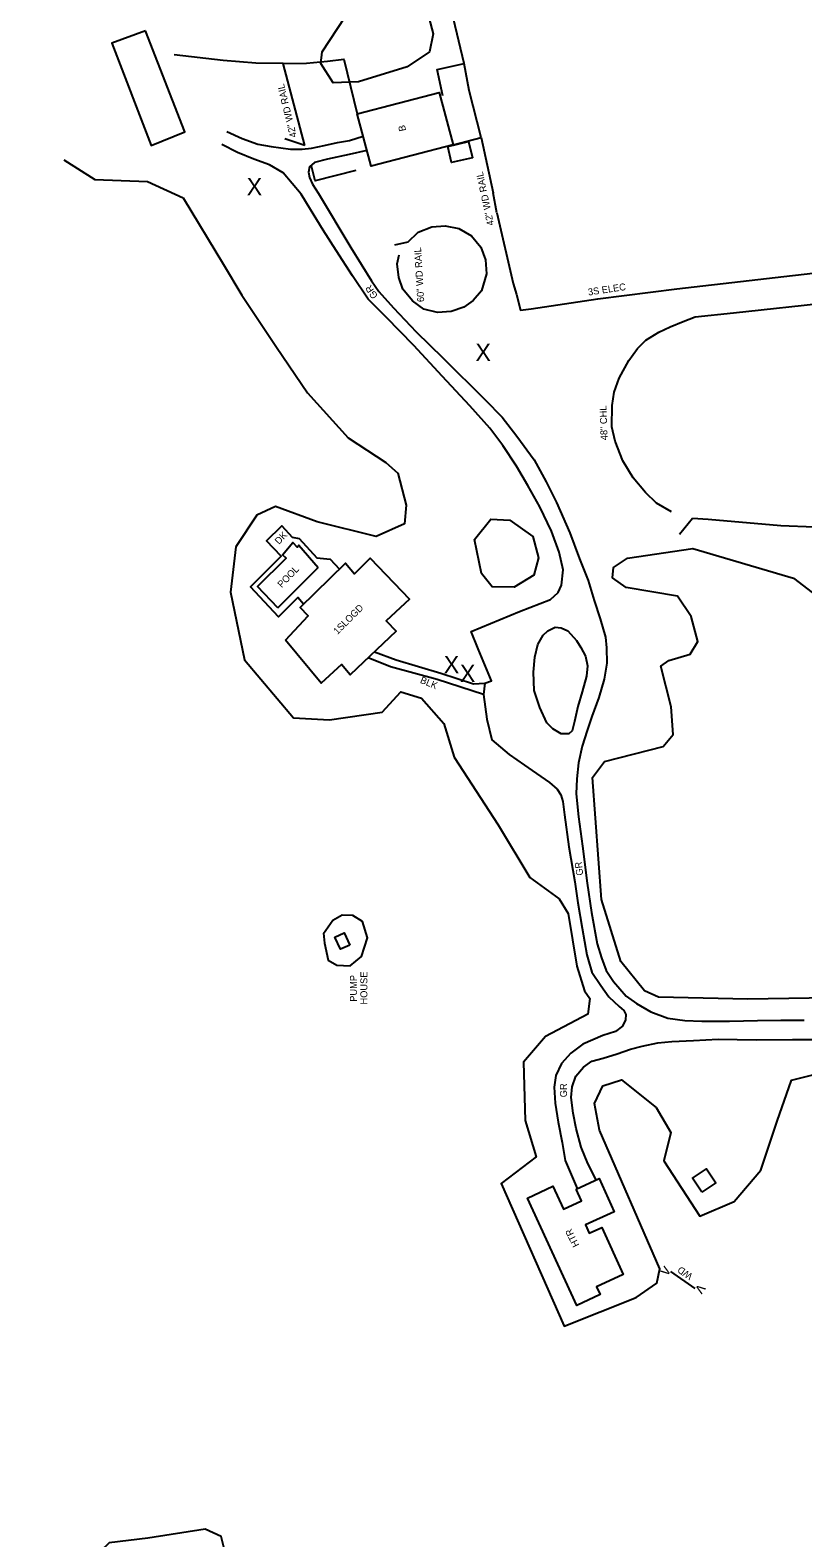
# Model space of a CAD drawing. Extents: x 2030130 to 2036320, y 723205 to 762423.
# Drawn here: x 2033438 to 2033884, y 736507 to 737377 of the extents above; entities that cross this region are included whole.
import ezdxf

# ---------------------------------------------------------------- set-up
doc = ezdxf.new("R2010")
doc.units = 0
for name, color, linetype in [('Draft_Station Labels Major', 7, 'Continuous'), ('Draft_Station Tics Major', 7, 'Continuous'), ('Draft_Station Tics Minor', 7, 'Continuous'), ('Exist Terrain Model Ground Surface', 7, 'Continuous'), ('Old_Level_23', 7, 'Continuous'), ('Old_Level_28', 7, 'Continuous'), ('Prop Alignment Horizontal', 7, 'Continuous'), ('Prop Alignment Vertical', 7, 'Continuous')]:
    doc.layers.add(name, color=color, linetype=linetype)

msp = doc.modelspace()

# ---------------------------------------------------------------- linework, layer by layer
at = {"layer": 'Draft_Station Labels Major'}
for points in [[(2033551.47, 737318.7), (2033560.28, 737314.7), (2033569.25, 737311.43), (2033577.08, 737310.08), (2033588.19, 737308.38), (2033594.96, 737308.45), (2033600.29, 737309.08), (2033607.49, 737310.58), (2033615.28, 737312.26), (2033622.21, 737313.44), (2033630, 737315.95)], [(2033738.15, 737048.45), (2033742.53, 737052.52), (2033744.49, 737056.73), (2033745.4, 737065.63), (2033743.01, 737075.88), (2033738.76, 737087.88), (2033731.95, 737101.93), (2033725.02, 737114.27), (2033718.45, 737125.49), (2033710.59, 737137.4), (2033703.2, 737147.39), (2033691.63, 737160.33), (2033675.71, 737177.53), (2033659.29, 737195.07), (2033643.28, 737211.42), (2033632.89, 737221.89), (2033623.89, 737235.28), (2033614.47, 737249.93), (2033607.06, 737261.76), (2033599.66, 737273.66), (2033594.34, 737282.48), (2033583.93, 737294.85), (2033576.05, 737299.48), (2033567.09, 737302.69), (2033557.55, 737306.45), (2033548.5, 737311.17)], [(2033632.24, 737307.68), (2033621.97, 737305.31), (2033609.49, 737302.71), (2033601.95, 737300.7), (2033599.06, 737298.35), (2033598.51, 737295.09), (2033599.21, 737292.11), (2033600.94, 737288.26), (2033604.39, 737282.78), (2033622.92, 737251.78), (2033634.83, 737232.47), (2033639.05, 737226.24), (2033647.64, 737216.87), (2033660.7, 737203.1), (2033676.08, 737188.02), (2033700.39, 737163.69), (2033710.14, 737153.76), (2033718.69, 737142.81), (2033728.73, 737129.13), (2033735.59, 737116.53), (2033741.61, 737104.6), (2033749.24, 737086.92), (2033754.78, 737071.99), (2033759.8, 737059.57), (2033763.34, 737047.92), (2033766.71, 737037.45), (2033769.82, 737026.86), (2033770.49, 737020.73), (2033770.63, 737011.74), (2033769.11, 737002.53), (2033766.05, 736991.98), (2033761.86, 736980.94), (2033759.2, 736972.95), (2033756.31, 736963.97), (2033754.26, 736954.25), (2033753.28, 736945.09), (2033752.83, 736936.44), (2033754.21, 736923.01), (2033756.48, 736906.14), (2033759.28, 736884.73), (2033761.81, 736867.92), (2033765.02, 736849.71), (2033767.56, 736841.63)], [(2033700.22, 737000.33), (2033704.07, 737001.67), (2033696.45, 737020.02), (2033692.28, 737030), (2033720.27, 737041.61), (2033738.15, 737048.45)], [(2033731.95, 736986.27), (2033728.75, 736996.01), (2033728.34, 737006.59), (2033729.11, 737015.3), (2033730.77, 737022.54), (2033733.94, 737027.96), (2033736.64, 737030.51), (2033740.84, 737032.55), (2033744.3, 737032.12), (2033748.19, 737030.44), (2033753.02, 737024.92), (2033755.66, 737020.77), (2033758.34, 737015.83), (2033759.42, 737010.22), (2033758.79, 737004.2), (2033756.43, 736995.15), (2033753.89, 736986.75), (2033752, 736978.21), (2033750.53, 736972.8), (2033748.64, 736970.96), (2033744.24, 736970.95), (2033739.53, 736973.84), (2033735.96, 736977.43), (2033731.95, 736986.27)], [(2033699.5, 736993.65), (2033701.39, 736979.55), (2033704.33, 736967.58), (2033714.26, 736959.03), (2033727.45, 736949.85), (2033737.55, 736942.93), (2033741.91, 736939.13), (2033744.04, 736935.85), (2033745.17, 736931.88), (2033746.14, 736924.3), (2033748.69, 736905.78), (2033752.11, 736885.6), (2033753.92, 736873.53), (2033756.39, 736858.82), (2033759.1, 736843.52), (2033759.77, 736840.82)], [(2033759.77, 736840.82), (2033761.93, 736833.48), (2033767.13, 736825.65), (2033771.79, 736819.27), (2033777.64, 736813.56), (2033780.36, 736811.27), (2033781.52, 736809.09), (2033781.42, 736805.85), (2033779.61, 736802.27), (2033775.55, 736799.1), (2033768.21, 736796.8), (2033756.69, 736791.85), (2033749.84, 736786.75), (2033744.52, 736780.63), (2033741.25, 736773.86), (2033740.19, 736767.08), (2033740.8, 736757.84), (2033742.52, 736746.88), (2033744.86, 736735.06), (2033746.61, 736724.75), (2033753.57, 736708.54)], [(2033767.56, 736841.63), (2033770.18, 736834.34), (2033774.45, 736827.97), (2033781.64, 736819.63), (2033787.67, 736815.35), (2033795.89, 736810.47), (2033805.83, 736806.97), (2033815.65, 736805.49), (2033825.37, 736805.24), (2033841.27, 736805.18), (2033857.51, 736805.49), (2033871.01, 736805.64), (2033884.45, 736805.73)], [(2033764.45, 736713.52), (2033759.59, 736723.03), (2033755.74, 736732.44), (2033752.85, 736743.18), (2033751.12, 736752.06), (2033750.05, 736761.18), (2033750.64, 736767.26), (2033752.79, 736773.42), (2033757.04, 736778.54), (2033761.96, 736782.08), (2033768.44, 736783.88), (2033776.5, 736786.34), (2033784.18, 736789.02), (2033790.99, 736790.68), (2033799.94, 736792.66), (2033808.08, 736793.37), (2033820.49, 736794.07), (2033834.79, 736794.71), (2033856.72, 736794.46), (2033877.62, 736794.56), (2033896.24, 736794.48)]]:
    msp.add_lwpolyline(points, dxfattribs=at)
at = {"layer": 'Draft_Station Tics Major'}
for points in [[(2033606.43, 737364.57), (2033624.2, 737391.48), (2033637.45, 737415.62), (2033649.06, 737423.39), (2033658.43, 737420.22), (2033670.45, 737375.08), (2033668.41, 737364.71), (2033655.42, 737356.01), (2033627.36, 737347.36), (2033612.67, 737346.82), (2033605.65, 737357.84), (2033606.43, 737364.57)], [(2033457.49, 737302.26), (2033475.32, 737290.94), (2033505.6, 737289.87), (2033526.18, 737280.39), (2033549.59, 737241.87), (2033560.08, 737224.19), (2033580.07, 737194.26), (2033598.04, 737167.87), (2033621.42, 737141.9), (2033643.21, 737127.56), (2033649.99, 737121.38), (2033654.86, 737102.89), (2033653.97, 737092.3), (2033637.54, 737084.86), (2033603.61, 737093.37), (2033579.53, 737102.17), (2033568.77, 737097.27), (2033556.66, 737078.89), (2033553.58, 737052.72), (2033561.72, 737013.68), (2033589.91, 736980.23), (2033610.73, 736979.05), (2033640.98, 736983.58), (2033651.75, 736995.24), (2033663.61, 736991.61), (2033676.51, 736976.95), (2033682.51, 736957.47), (2033707.84, 736918.51), (2033726.27, 736888.05), (2033743.1, 736875.78), (2033748.26, 736867.33), (2033753.37, 736836.87)], [(2033698.32, 737063.6), (2033694.26, 737083.22), (2033703.67, 737094.92), (2033714.66, 737094.41), (2033727.91, 737084.95), (2033731.21, 737072.49), (2033728.42, 737062.53), (2033717.21, 737055.71), (2033704.47, 737055.89), (2033698.32, 737063.6)], [(2033792.32, 736822.69), (2033778.71, 736839.69), (2033767.46, 736875.32), (2033762.35, 736945.75), (2033769.18, 736955.01), (2033803.03, 736963.69), (2033808.83, 736970.66), (2033807.74, 736986.53), (2033801.67, 737010.07), (2033806.4, 737013.41), (2033818.66, 737016.91), (2033823.13, 737024.31), (2033819.29, 737038.71), (2033811.33, 737050.53), (2033781.74, 737055.44), (2033773.79, 737061.08), (2033774.35, 737067.04), (2033782.42, 737072.41), (2033820.23, 737077.88), (2033878.24, 737060.76), (2033918.86, 737029.66)], [(2033607.2, 736855.93), (2033607.8, 736850.16), (2033609.96, 736840.44), (2033614.95, 736837.4), (2033622.65, 736837.15), (2033629.08, 736842.43), (2033632.56, 736853.28), (2033629.73, 736862.64), (2033624.11, 736866.21), (2033617.98, 736866.28), (2033612.52, 736863.19), (2033607.19, 736855.54)], [(2033753.37, 736836.87), (2033757.72, 736822.68), (2033760.84, 736818.16), (2033759.59, 736809.16), (2033735.12, 736796.29), (2033722.53, 736781.5), (2033723.55, 736747.8), (2033729.8, 736726.82), (2033709.68, 736711.5), (2033746.07, 736629.15), (2033787.58, 736645.69), (2033799.39, 736653.97), (2033801.19, 736662.18), (2033766.27, 736742.19), (2033763.5, 736757.67), (2033768.26, 736767.9), (2033779.14, 736771.2), (2033799.02, 736755.36), (2033807.59, 736740.85), (2033803.41, 736724.63), (2033824.3, 736692.6), (2033844, 736701), (2033859.4, 736719.17), (2033868.79, 736747.53), (2033877.05, 736771.11), (2033914.87, 736780.47)], [(2034087.97, 736821.64), (2033851.91, 736817.84), (2033800.39, 736818.95), (2033792.32, 736822.69)], [(2033571.43, 736486.26), (2033555.5, 736487.36), (2033551.67, 736493.83), (2033548.08, 736507.8), (2033538.98, 736511.94), (2033505.92, 736506.85), (2033483.52, 736504.11), (2033473.79, 736494.62), (2033468.28, 736473.06), (2033459.23, 736467), (2033438.03, 736465.76)]]:
    msp.add_lwpolyline(points, dxfattribs=at)
at = {"layer": 'Draft_Station Tics Minor'}
msp.add_lwpolyline([(2033821.54, 736650.77), (2033807.51, 736660.75)], dxfattribs=at)
at = {"layer": 'Exist Terrain Model Ground Surface'}
for points in [[(2033675.98, 737339.32), (2033672.69, 737354.35), (2033688.31, 737357.81), (2033682.15, 737383.74), (2033672.12, 737429.28), (2033663.5, 737462.72), (2033656.52, 737489.39), (2033665.21, 737490.19)], [(2033596.45, 737310.59), (2033583.99, 737357.89), (2033568.09, 737358.03), (2033549.35, 737359.54), (2033521.02, 737362.91)], [(2033583.99, 737357.89), (2033597.3, 737358.03)], [(2033597.3, 737358.03), (2033609.46, 737359.31)], [(2033609.46, 737359.31), (2033619.01, 737360.33), (2033626.51, 737328.82)], [(2033691.19, 737342.4), (2033688.31, 737357.81)], [(2033698.17, 737315.27), (2033691.19, 737342.4)], [(2033596.45, 737310.59), (2033584.82, 737314.51)], [(2033681.94, 737310.92), (2033698.17, 737315.27), (2033704.94, 737283.26)], [(2033625.89, 737296.17), (2033602.38, 737290.14), (2033600.34, 737298.74)], [(2033707.14, 737271.66), (2033704.94, 737283.26)], [(2033707.14, 737271.66), (2033716.66, 737230.89), (2033718.57, 737224.62)], [(2033655.79, 737254.69), (2033661.83, 737260.58), (2033669.61, 737263.61), (2033677.26, 737264.3), (2033685.24, 737262.7), (2033692.55, 737258.52), (2033697.9, 737251.91), (2033700.69, 737244.65), (2033701.1, 737236.43), (2033698.28, 737226.73), (2033693.49, 737221.13), (2033688.16, 737217.24), (2033680.72, 737214.78), (2033672.88, 737214.09), (2033665.05, 737216.15), (2033658.47, 737220.84), (2033652.99, 737227.64), (2033650.64, 737234.3), (2033649.7, 737242.28), (2033650.76, 737247.4)], [(2033655.79, 737254.69), (2033648.12, 737253.02)], [(2033718.57, 737224.62), (2033720.85, 737215.49), (2033726.87, 737216.23), (2033765.32, 737222.16), (2033810.99, 737227.82), (2033899.31, 737238.04), (2033970.19, 737246.85)], [(2033807.8, 737099.23), (2033799.27, 737104.11), (2033792.8, 737110.23), (2033785.81, 737118.71), (2033779.77, 737128.53), (2033775.34, 737140.01), (2033773.56, 737148.27), (2033773.59, 737160.6), (2033774.85, 737168.12), (2033777.69, 737176.32), (2033783.27, 737186.46), (2033788.29, 737193.36), (2033793, 737198.18), (2033800.5, 737202.79), (2033807.11, 737205.92), (2033814.56, 737209.03), (2033821.49, 737211.7), (2033843.59, 737213.93), (2033900.37, 737220.18)], [(2033819.95, 737095.29), (2033812.58, 737086.12)], [(2033890.29, 737090.33), (2033871.01, 737091.14), (2033829.06, 737094.77), (2033819.95, 737095.29)], [(2033595.63, 737045.88), (2033592.33, 737049.68), (2033581.3, 737038.44), (2033565.08, 737055.92), (2033582.7, 737073.56), (2033574.26, 737082.41), (2033583.11, 737091.13), (2033589.13, 737084.46), (2033593.12, 737083.68), (2033603.31, 737072.49), (2033611.12, 737071.79), (2033616.35, 737066.09)], [(2033636.65, 737018.37), (2033649.16, 737013.77), (2033674.89, 737005.99), (2033693.64, 736999.8), (2033700.22, 737000.33), (2033699.5, 736993.65), (2033672.75, 737002.31), (2033645.89, 737009.66), (2033632.95, 737014.88)]]:
    msp.add_lwpolyline(points, dxfattribs=at)
for points in [[(2033504.54, 737376.81), (2033485.16, 737369.62), (2033507.77, 737310.54), (2033527.17, 737318.52)], [(2033681.94, 737310.92), (2033634.7, 737298.59), (2033626.51, 737328.82), (2033673.88, 737341.14)], [(2033693.07, 737303.55), (2033680.99, 737300.77), (2033678.85, 737310.09), (2033690.79, 737312.81)], [(2033585.19, 737025.07), (2033598.38, 737039.09), (2033593.7, 737043.99), (2033619.86, 737069.51), (2033625.16, 737063.29), (2033634.16, 737072.42), (2033656.69, 737048.69), (2033643.42, 737036.16), (2033649.18, 737030.19), (2033622.5, 737005.01), (2033617.59, 737011.09), (2033605.93, 737000.21)], [(2033622.31, 736849.1), (2033616.94, 736846.63), (2033613.7, 736853.67), (2033619.07, 736856.14)], [(2033752.88, 736708.22), (2033766.11, 736714.28), (2033774.89, 736695.14), (2033758.27, 736687.54), (2033760.44, 736682.77), (2033767.72, 736686.11), (2033779.98, 736658.89), (2033764.72, 736651.81), (2033766.77, 736647.38), (2033753.28, 736641.11), (2033724.81, 736703.05), (2033739.42, 736709.83), (2033745.53, 736696.7), (2033755.93, 736701.55)], [(2033825.32, 736706.48), (2033819.96, 736714.52), (2033828.05, 736719.91), (2033833.41, 736711.86)]]:
    msp.add_lwpolyline(points, close=True, dxfattribs=at)
at = {"layer": 'Prop Alignment Horizontal'}
for points in [[(2033580.84, 737043.77), (2033569.14, 737056.04), (2033585.58, 737072.33), (2033583.62, 737074.34), (2033589.43, 737081.34), (2033592.09, 737078.79), (2033592.97, 737079.87), (2033604.14, 737067.03)], [(2033580.84, 737043.77), (2033604.14, 737067.03)]]:
    msp.add_lwpolyline(points, dxfattribs=at)

# ---------------------------------------------------------------- texts
at = {"layer": 'Draft_Station Tics Major'}
for p in [(2033562.9, 737281.83), (2033694.8, 737186.18), (2033676.55, 737005.98), (2033685.86, 737000.89)]:
    msp.add_text('X', height=10, dxfattribs=at).set_placement(p)
at = {"layer": 'Draft_Station Tics Minor'}
for rotation, p in [(54.8202, (2033805.35, 736657.69)), (234.33849, (2033823.72, 736653.81))]:
    msp.add_text('v', height=6.6, rotation=rotation, dxfattribs=at).set_placement(p)
at = {"layer": 'Old_Level_23'}
for rotation, p in [(123.30862, (2033638.77, 737223.74)), (97.50024, (2033757.03, 736889.43)), (90.00002, (2033747.56, 736761.21))]:
    msp.add_text('GR', height=4, rotation=rotation, dxfattribs=at).set_placement(p)
at = {"layer": 'Old_Level_28'}
for s, rotation, p in [('42" WD RAIL', 103.57166, (2033591.8, 737315.7)), ('B', 102.24271, (2033654.85, 737319.21)), ('42" WD RAIL', 101.87886, (2033705.57, 737264.78)), ('60" WD RAIL', 93.34382, (2033665.29, 737220.33)), ('3S ELEC', 8.46339, (2033760.02, 737223.95)), ('48" CHL', 92.07134, (2033771.05, 737140.53)), ('DK', 46.39817, (2033581.5, 737080.02)), ('1SLOGD', 44.92952, (2033615.23, 737028.05)), ('BLK', 337.39, (2033662.57, 737000.55)), ('PUMP', 90.00002, (2033626.47, 736816.35)), ('HOUSE', 90.00002, (2033632.47, 736814.76)), ('HTR', 115.86848, (2033754.82, 736675.89)), ('WD', 145.69568, (2033820.45, 736658.88))]:
    msp.add_text(s, height=4, rotation=rotation, dxfattribs=at).set_placement(p)
at = {"layer": 'Prop Alignment Vertical'}
msp.add_text('POOL', height=4, rotation=45.98897, dxfattribs=at).set_placement((2033583.06, 737055.02))

doc.saveas('drawing.dxf')
